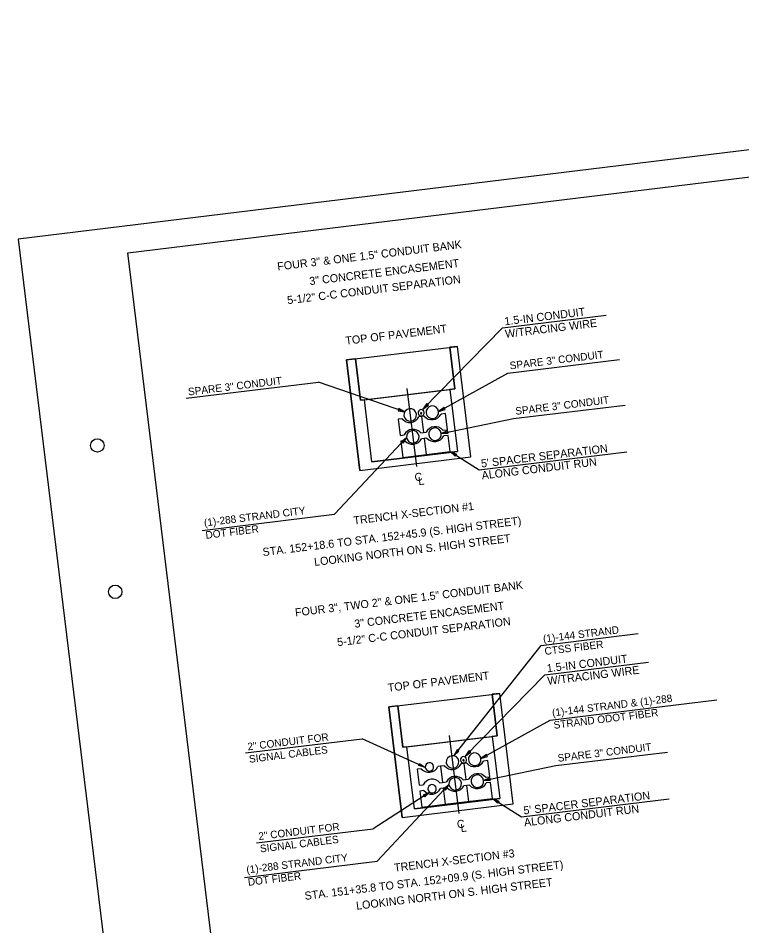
# Model space of a CAD drawing. Extents: x 91401 to 1830080, y 35587 to 712188.
# Drawn here: x 1827840 to 1828380, y 711457 to 712134 of the extents above; entities that cross this region are included whole.
import ezdxf

# ---------------------------------------------------------------- set-up
doc = ezdxf.new("R2010")
doc.units = 0
for name, color, linetype in [('Default', 7, 'Continuous'), ('SH_Border', 7, 'Continuous'), ('SH_Cut_Line', 7, 'Continuous'), ('SH_Text', 7, 'Continuous')]:
    doc.layers.add(name, color=color, linetype=linetype)

# ---------------------------------------------------------------- blocks, each defined once
blk = doc.blocks.new('POINT_DISPLAY')
at = {"layer": 'Default'}
blk.add_line((0, 0), (0, 0), dxfattribs=at)

msp = doc.modelspace()

# ---------------------------------------------------------------- linework, layer by layer
at = {"layer": 'SH_Border'}
msp.add_lwpolyline([(1827921.45, 711959.1), (1829172.16, 712111.82), (1829273.97, 711278.01), (1828023.26, 711125.29)], close=True, dxfattribs=at)
for centre in [(1827898.71, 711815.29), (1827912.05, 711706.1)]:
    msp.add_circle(centre, 5, dxfattribs=at)
at = {"layer": 'SH_Cut_Line'}
msp.add_lwpolyline([(1827946.27, 711095.75), (1829296.25, 711260.58), (1829189.59, 712134.09), (1827839.62, 711969.26)], close=True, dxfattribs=at)
at = {"layer": 'SH_Text'}
for p, q in [((1828200.96, 711903.16), (1828278.33, 711912.6)), ((1828141.64, 711842.45), (1828200.96, 711903.16)), ((1828167.38, 711889.22), (1828161.79, 711888.54)), ((1828165.57, 711857.58), (1828161.79, 711888.54)), ((1828177.46, 711806.7), (1828167.38, 711889.22)), ((1828091.25, 711879.93), (1828084.54, 711879.11)), ((1828084.54, 711879.11), (1828094.62, 711796.59)), ((1828095.03, 711848.97), (1828091.25, 711879.93)), ((1828205.1, 711869.21), (1828288.39, 711879.38)), ((1828153.36, 711840.66), (1828205.1, 711869.21)), ((1827964.98, 711850.49), (1828063.76, 711862.55)), ((1828128.07, 711840.39), (1828063.76, 711862.55)), ((1828129.75, 711857.8), (1828136.84, 711799.71)), ((1828161.73, 711857.12), (1828167.39, 711810.8)), ((1828098.01, 711849.33), (1828095.03, 711848.97)), ((1828103.66, 711803.01), (1828098.01, 711849.33)), ((1828209.24, 711835.31), (1828292.53, 711845.48)), ((1828155.36, 711824.31), (1828209.24, 711835.31)), ((1828129.49, 711821.16), (1828075.8, 711763.95)), ((1828094.62, 711796.59), (1828177.46, 711806.7)), ((1828094.62, 711796.59), (1828177.46, 711806.7)), ((1828103.66, 711803.01), (1828167.39, 711810.8)), ((1828103.66, 711803.01), (1828167.39, 711810.8)), ((1828103.66, 711803.01), (1828167.39, 711810.8)), ((1828167.39, 711810.8), (1828103.66, 711803.01)), ((1828162.01, 711810.75), (1828183.51, 711797.03)), ((1828183.51, 711797.03), (1828293.71, 711810.48)), ((1827977.02, 711751.89), (1828075.8, 711763.95)), ((1828229.91, 711666.08), (1828302.4, 711674.93)), ((1828164.83, 711583.77), (1828229.91, 711666.08)), ((1828232.57, 711644.27), (1828309.94, 711653.72)), ((1828173.25, 711583.57), (1828232.57, 711644.27)), ((1828198.99, 711630.34), (1828193.4, 711629.66)), ((1828209.07, 711547.82), (1828198.99, 711630.34)), ((1828197.18, 711598.7), (1828193.4, 711629.66)), ((1828236.71, 711610.33), (1828360.94, 711625.5)), ((1828122.86, 711621.05), (1828116.15, 711620.23)), ((1828116.15, 711620.23), (1828126.23, 711537.71)), ((1828126.64, 711590.09), (1828122.86, 711621.05)), ((1828184.97, 711581.78), (1828236.71, 711610.33)), ((1828009.34, 711585.88), (1828096.25, 711596.49)), ((1828143.44, 711575.13), (1828096.25, 711596.49)), ((1828161.36, 711598.92), (1828168.45, 711540.83)), ((1828193.34, 711598.23), (1828199, 711551.91)), ((1828129.62, 711590.45), (1828126.64, 711590.09)), ((1828135.27, 711544.13), (1828129.62, 711590.45)), ((1828240.85, 711576.43), (1828324.14, 711586.6)), ((1828186.97, 711565.43), (1828240.85, 711576.43)), ((1828161.1, 711562.28), (1828107.41, 711505.07)), ((1828146.82, 711556.56), (1828104.45, 711529.35)), ((1828135.27, 711544.13), (1828199, 711551.91)), ((1828135.27, 711544.13), (1828199, 711551.91)), ((1828135.27, 711544.13), (1828199, 711551.91)), ((1828199, 711551.91), (1828135.27, 711544.13)), ((1828193.62, 711551.87), (1828215.12, 711538.15)), ((1828215.12, 711538.15), (1828325.32, 711551.6)), ((1828126.23, 711537.71), (1828209.07, 711547.82)), ((1828126.23, 711537.71), (1828209.07, 711547.82)), ((1828017.54, 711518.74), (1828104.45, 711529.35)), ((1828008.63, 711493.01), (1828107.41, 711505.07))]:
    msp.add_line(p, q, dxfattribs=at)
for points in [[(1828084.54, 711879.11), (1828155.08, 711887.72), (1828167.38, 711889.22), (1828167.38, 711889.22)], [(1828091.25, 711879.93), (1828095.03, 711848.97), (1828165.57, 711857.58), (1828161.79, 711888.54)], [(1828161.79, 711888.54), (1828165.57, 711857.58), (1828161.73, 711857.12)], [(1828177.46, 711806.7), (1828167.38, 711889.22)], [(1828094.62, 711796.59), (1828084.54, 711879.11)], [(1828098.01, 711849.33), (1828138.57, 711854.29), (1828161.73, 711857.12), (1828167.39, 711810.8)], [(1828098.01, 711849.33), (1828156.38, 711856.46), (1828161.73, 711857.12), (1828167.39, 711810.8)], [(1828098.01, 711849.33), (1828120.76, 711852.11), (1828161.73, 711857.12), (1828167.39, 711810.8)], [(1828103.66, 711803.01), (1828098.01, 711849.33)], [(1828103.66, 711803.01), (1828098.01, 711849.33)], [(1828126.21, 711835.17), (1828123.28, 711834.81), (1828124.75, 711822.77)], [(1828142.71, 711837.18), (1828138.66, 711836.69)], [(1828140.68, 711836.94), (1828142.15, 711824.9)], [(1828156.63, 711826.67), (1828160.02, 711827.08), (1828158.55, 711839.12), (1828155.16, 711838.7)], [(1828124.75, 711822.77), (1828127.67, 711823.13)], [(1828126.74, 711806.44), (1828162.01, 711810.75), (1828160.54, 711822.79), (1828157.15, 711822.37)], [(1828140.13, 711824.65), (1828144.18, 711825.15)], [(1828144.7, 711820.85), (1828140.65, 711820.36)], [(1828142.68, 711820.6), (1828144.15, 711808.57)], [(1828128.2, 711818.84), (1828125.27, 711818.48), (1828126.74, 711806.44)], [(1828116.15, 711620.23), (1828186.69, 711628.84), (1828198.99, 711630.34), (1828198.99, 711630.34)], [(1828209.07, 711547.82), (1828198.99, 711630.34)], [(1828122.86, 711621.05), (1828126.64, 711590.09), (1828197.18, 711598.7), (1828193.4, 711629.66)], [(1828193.4, 711629.66), (1828197.18, 711598.7), (1828193.34, 711598.23)], [(1828126.23, 711537.71), (1828116.15, 711620.23)], [(1828129.62, 711590.45), (1828170.18, 711595.41), (1828193.34, 711598.23), (1828199, 711551.91)], [(1828129.62, 711590.45), (1828187.99, 711597.58), (1828193.34, 711598.23), (1828199, 711551.91)], [(1828129.62, 711590.45), (1828152.37, 711593.23), (1828193.34, 711598.23), (1828199, 711551.91)], [(1828135.27, 711544.13), (1828129.62, 711590.45)], [(1828135.27, 711544.13), (1828129.62, 711590.45)], [(1828154.89, 711575.93), (1828152.86, 711575.68)], [(1828157.81, 711576.29), (1828154.89, 711575.93), (1828156.36, 711563.89)], [(1828174.32, 711578.3), (1828170.27, 711577.81)], [(1828172.29, 711578.06), (1828173.76, 711566.02)], [(1828188.24, 711567.79), (1828191.63, 711568.2), (1828190.16, 711580.24), (1828186.77, 711579.82)], [(1828140.41, 711574.16), (1828137.49, 711573.81), (1828138.96, 711561.77), (1828141.88, 711562.13)], [(1828154.33, 711563.65), (1828156.36, 711563.89)], [(1828156.36, 711563.89), (1828159.28, 711564.25)], [(1828158.35, 711547.56), (1828193.62, 711551.87), (1828192.15, 711563.91), (1828188.76, 711563.49)], [(1828171.74, 711565.77), (1828175.79, 711566.27)], [(1828142.41, 711557.83), (1828139.48, 711557.47), (1828140.95, 711545.44), (1828158.35, 711547.56)], [(1828156.88, 711559.6), (1828154.86, 711559.35)], [(1828159.81, 711559.96), (1828156.88, 711559.6), (1828158.35, 711547.56)], [(1828176.31, 711561.97), (1828172.26, 711561.48)], [(1828174.29, 711561.72), (1828175.76, 711549.69)]]:
    msp.add_lwpolyline(points, dxfattribs=at)
for points in [[(1828145.75, 711845.41), (1828144.57, 711846.58), (1828141.64, 711842.45)], [(1828123.61, 711842.8), (1828123.07, 711841.23), (1828128.07, 711840.39)], [(1828158.2, 711842.18), (1828157.44, 711843.67), (1828153.36, 711840.66)], [(1828126.67, 711816.94), (1828125.46, 711818.08), (1828129.49, 711821.16)], [(1828160.42, 711824.51), (1828160.09, 711826.14), (1828155.36, 711824.31)], [(1828166.67, 711808.75), (1828165.77, 711807.35), (1828162.01, 711810.75)], [(1828168.58, 711587.17), (1828167.28, 711588.2), (1828164.83, 711583.77)], [(1828177.36, 711586.53), (1828176.18, 711587.7), (1828173.25, 711583.57)], [(1828189.81, 711583.3), (1828189.05, 711584.79), (1828184.97, 711581.78)], [(1828138.55, 711576.43), (1828139.23, 711577.95), (1828143.44, 711575.13)], [(1828158.28, 711558.06), (1828157.07, 711559.2), (1828161.1, 711562.28)], [(1828192.03, 711565.63), (1828191.7, 711567.26), (1828186.97, 711565.43)], [(1828143.06, 711553.15), (1828142.16, 711554.56), (1828146.82, 711556.56)], [(1828198.28, 711549.87), (1828197.38, 711548.47), (1828193.62, 711551.87)]]:
    msp.add_lwpolyline(points, close=True, dxfattribs=at)
for centre, radius, start, end in [((1828132.16, 711838.07), 4.7, 6.96143, 186.96143), ((1828140.35, 711839.67), 2.35, 6.96143, 186.96143), ((1828140.35, 711839.67), 2.35, 186.96143, 6.96143), ((1828140.33, 711839.27), 0.5, 6.96143, 186.96143), ((1828148.7, 711840.09), 4.7, 6.96143, 186.96143), ((1828148.7, 711840.09), 4.7, 186.96143, 6.96143), ((1828131.94, 711839.92), 7.45, 219.64855, 334.27431), ((1828132.16, 711838.07), 4.7, 186.96143, 6.96143), ((1828140.33, 711839.27), 0.5, 186.96143, 6.96143), ((1828148.45, 711841.94), 7.45, 219.64855, 334.27431), ((1828134.39, 711819.9), 7.45, 39.64855, 154.27431), ((1828134.15, 711821.73), 4.7, 6.96143, 186.96143), ((1828150.89, 711821.91), 7.45, 39.64855, 154.27431), ((1828150.69, 711823.74), 4.7, 6.96143, 186.96143), ((1828133.94, 711823.59), 7.45, 219.64855, 334.27431), ((1828134.15, 711821.73), 4.7, 186.96143, 6.96143), ((1828150.44, 711825.61), 7.45, 219.64855, 334.27431), ((1828150.69, 711823.74), 4.7, 186.96143, 6.96143), ((1828163.77, 711579.19), 4.7, 6.96143, 186.96143), ((1828171.96, 711580.79), 2.35, 6.96143, 186.96143), ((1828180.31, 711581.21), 4.7, 6.96143, 186.96143), ((1828146.15, 711578.92), 7.45, 219.64855, 334.27431), ((1828146.55, 711575.51), 3.13, 6.96143, 186.96143), ((1828146.55, 711575.51), 3.13, 186.96143, 6.96143), ((1828163.55, 711581.04), 7.45, 219.64855, 334.27431), ((1828163.77, 711579.19), 4.7, 186.96143, 6.96143), ((1828171.96, 711580.79), 2.35, 186.96143, 6.96143), ((1828171.94, 711580.39), 0.5, 6.96143, 186.96143), ((1828171.94, 711580.39), 0.5, 186.96143, 6.96143), ((1828180.06, 711583.06), 7.45, 219.64855, 334.27431), ((1828180.31, 711581.21), 4.7, 186.96143, 6.96143), ((1828182.5, 711563.03), 7.45, 39.64855, 154.27431), ((1828182.3, 711564.86), 4.7, 6.96143, 186.96143), ((1828148.6, 711558.89), 7.45, 39.64855, 154.27431), ((1828148.55, 711559.17), 3.13, 6.96143, 186.96143), ((1828166, 711561.02), 7.45, 39.64855, 154.27431), ((1828165.76, 711562.85), 4.7, 6.96143, 186.96143), ((1828165.76, 711562.85), 4.7, 186.96143, 6.96143), ((1828182.05, 711566.73), 7.45, 219.64855, 334.27431), ((1828182.3, 711564.86), 4.7, 186.96143, 6.96143), ((1828148.14, 711562.59), 7.45, 219.64855, 334.27431), ((1828148.55, 711559.17), 3.13, 186.96143, 6.96143), ((1828165.55, 711564.71), 7.45, 219.64855, 334.27431)]:
    msp.add_arc(centre, radius, start, end, dxfattribs=at)

# ---------------------------------------------------------------- block references
at = {"layer": 'SH_Text', "xscale": 1.5748, "yscale": 1.5748000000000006, "rotation": 6.96142799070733}
for p in [(1828136, 711806.57), (1828167.61, 711547.69)]:
    msp.add_blockref('POINT_DISPLAY', p, dxfattribs=at)

# ---------------------------------------------------------------- texts
at = {"layer": 'SH_Text'}
for s, height, p in [('FOUR 3" & ONE 1.5" CONDUIT BANK', 6, (1828033.37, 711945.78)), ('3" CONCRETE ENCASEMENT', 6, (1828057.3, 711934.89)), ('5-1/2" C-C CONDUIT SEPARATION', 6, (1828040.76, 711920.67)), ('1.5-IN CONDUIT', 6, (1828202.84, 711904.91)), ('W/TRACING WIRE', 6, (1828203.34, 711895.56)), ('TOP OF PAVEMENT', 6, (1828084.19, 711890.42)), ('SPARE 3" CONDUIT', 5.6, (1828206.77, 711872.02)), ('SPARE 3" CONDUIT', 5.6, (1827966.74, 711852.51)), ('SPARE 3" CONDUIT', 5.6, (1828210.91, 711838.11)), ("5' SPACER SEPARATION", 6, (1828185.38, 711798.78)), ('ALONG CONDUIT RUN', 6, (1828185.83, 711789.9)), ('C', 6, (1828135.8, 711788.48)), ('L', 6, (1828138.49, 711785.68)), ('TRENCH X-SECTION #1', 6, (1828090.19, 711756.29)), ('(1)-288 STRAND CITY ', 5.6, (1827978.66, 711754.87)), ('STA. 152+18.6 TO STA. 152+45.9 (S. HIGH STREET)', 6, (1828022.4, 711732.75)), ('DOT FIBER', 5.6, (1827979.79, 711745.6)), ('LOOKING NORTH ON S. HIGH STREET', 6, (1828060.86, 711725.36)), ('FOUR 3", TWO 2" & ONE 1.5" CONDUIT BANK', 6, (1828046.6, 711687.67)), ('3" CONCRETE ENCASEMENT', 6, (1828090.86, 711679.27)), ('5-1/2" C-C CONDUIT SEPARATION', 6, (1828078.04, 711665.51)), ('(1)-144 STRAND', 5.6, (1828231.65, 711668.25)), ('CTSS FIBER', 5.6, (1828232.78, 711658.98)), ('1.5-IN CONDUIT', 6, (1828234.45, 711646.03)), ('W/TRACING WIRE', 6, (1828234.95, 711636.68)), ('TOP OF PAVEMENT', 6, (1828115.8, 711631.54)), ('(1)-144 STRAND & (1)-288 ', 5.6, (1828238.38, 711613.14)), ('STRAND ODOT FIBER', 5.6, (1828239.51, 711603.87)), ('2" CONDUIT FOR ', 5.6, (1828011.12, 711587.79)), ('SIGNAL CABLES', 5.6, (1828012.25, 711578.52)), ('SPARE 3" CONDUIT', 5.6, (1828242.52, 711579.23)), ("5' SPACER SEPARATION", 6, (1828216.99, 711539.9)), ('ALONG CONDUIT RUN', 6, (1828217.44, 711531.02)), ('C', 6, (1828167.41, 711529.6)), ('2" CONDUIT FOR ', 5.6, (1828019.29, 711520.91)), ('L', 6, (1828170.1, 711526.8)), ('SIGNAL CABLES', 5.6, (1828020.42, 711511.65)), ('(1)-288 STRAND CITY ', 5.6, (1828010.27, 711495.99)), ('TRENCH X-SECTION #3', 6, (1828120.52, 711497.25)), ('STA. 151+35.8 TO STA. 152+09.9 (S. HIGH STREET)', 6, (1828053.72, 711476.26)), ('DOT FIBER', 5.6, (1828011.4, 711486.72)), ('LOOKING NORTH ON S. HIGH STREET', 6, (1828092.18, 711468.87))]:
    msp.add_text(s, height=height, rotation=6.96143, dxfattribs=at).set_placement(p)

doc.saveas('drawing.dxf')
